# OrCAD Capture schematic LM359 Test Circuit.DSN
size A; title: LM359 Dual, High Speed, Programmable, Current Mode; rev: 1.0; note: Datasheet: SNOSBT4C EVM: N/A
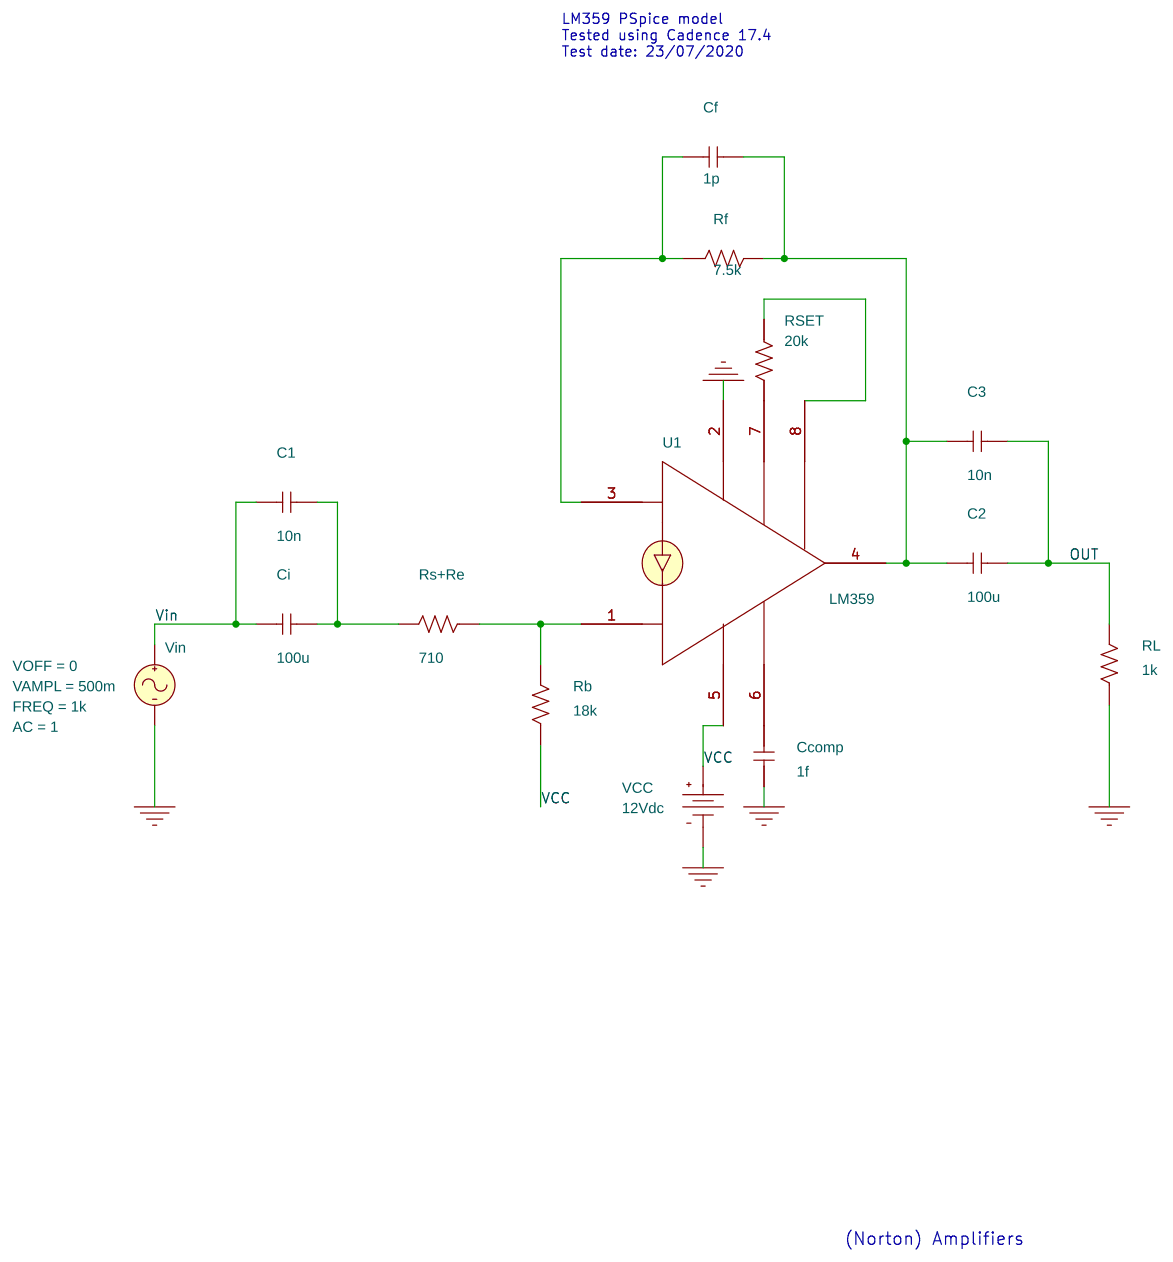
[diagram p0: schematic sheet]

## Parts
C1  10n  [RAD/CK05]
C2  100u  [RAD/CK05]
C3  10n  [RAD/CK05]
Ccomp  1f  [RAD/CK05]
Cf  1p  [RAD/CK05]
Ci  100u  [RAD/CK05]
Rb  18k  [AX/RC05]
Rf  7.5k  [AX/RC05]
RL  1k  [AX/RC05]
Rs+Re  710  [AX/RC05]
RSET  20k  [AX/RC05]
U1  LM359
VCC  VDC
Vin  VSIN

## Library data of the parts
C1-C3 Ccomp Cf Ci = C
Rb Rf RL Rs+Re RSET = R
U1 = LM359
VCC = VDC: DC: 12Vdc
Vin = VSIN: AC: 1; FREQ: 1k; VAMPL: 500m; VOFF: 0

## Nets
VCC: Rb.1 U1.5(VCC) VCC.0(+)
Vin: C1.2 Ci.2 Vin.1(+)
0: Ccomp.2 RL.1 U1.2(GND) VCC.1(-) Vin.2(-)
OUT: C2.1 C3.1 RL.2
N14296478: Cf.2 Rf.1 U1.3(I_IN-)
N14297923: C2.2 C3.2 Cf.1 Rf.2 U1.4(OUT)
N14297993: Rb.2 Rs+Re.1 U1.1(I_IN+)
N14298185: C1.1 Ci.1 Rs+Re.2
N14301400: RSET.1 U1.8(ISET_IN)
N14303319: RSET.2 U1.7(ISET_OUT)
N14303336: Ccomp.1 U1.6(COMP)

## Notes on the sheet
- LM359 PSpice model
  Tested using Cadence 17.4
  Test date: 23/07/2020
- (Norton) Amplifiers
